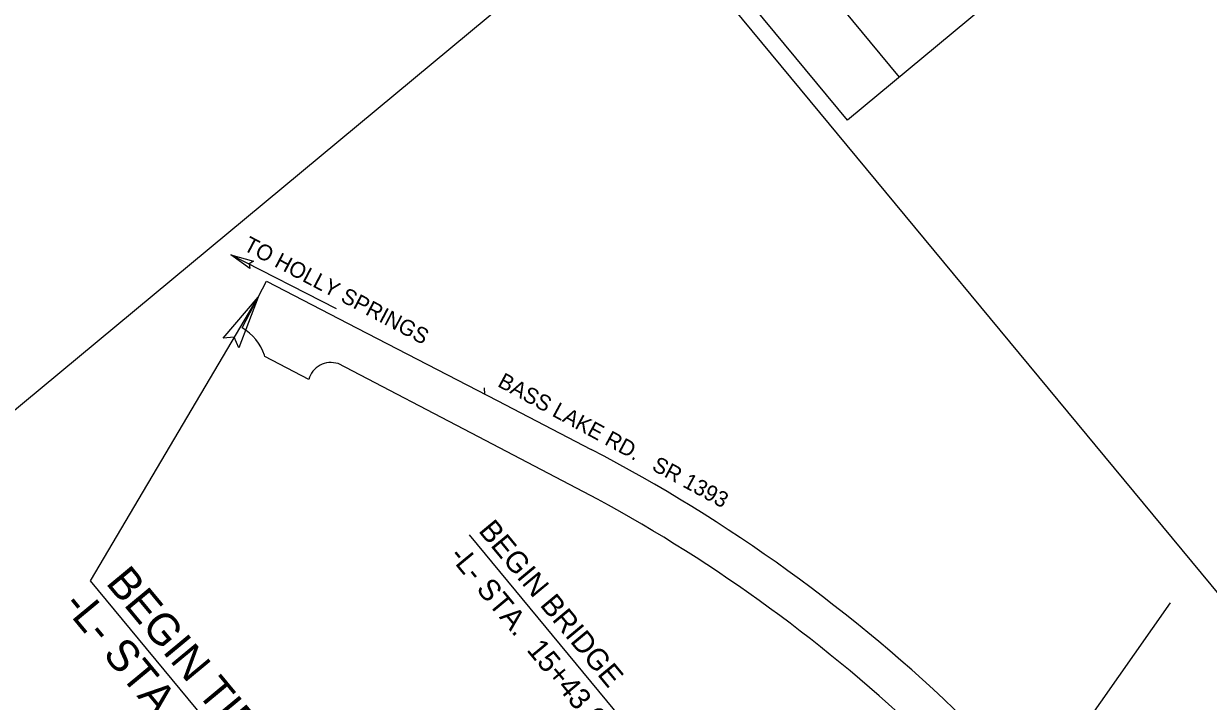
# Model space of a CAD drawing. Extents: x 2054826 to 2060231, y 685508 to 690809.
# Drawn here: x 2058198 to 2058951, y 688824 to 689255 of the extents above; entities that cross this region are included whole.
import ezdxf

# ---------------------------------------------------------------- set-up
doc = ezdxf.new("R2010")
doc.units = 0
for name, color, linetype in [('Default', 7, 'Continuous'), ('Old_Level_21', 7, 'Continuous'), ('Old_Level_9', 7, 'Continuous'), ('Prop Dimension Text', 7, 'Continuous'), ('Prop EOT', 7, 'Continuous'), ('Prop Horizontal Alignment Station Label', 7, 'Continuous'), ('Prop RDY Alternate Text Purple', 7, 'Continuous'), ('Prop Shade Medium', 7, 'Continuous'), ('Prop Terminator CELL', 7, 'Continuous')]:
    doc.layers.add(name, color=color, linetype=linetype)

msp = doc.modelspace()

# ---------------------------------------------------------------- linework, layer by layer
at = {"layer": 'Default'}
msp.add_line((2058396.86, 689073.63), (2058329.62, 689108), dxfattribs=at)
msp.add_lwpolyline([(2058776.37, 689968.05), (2059134.67, 689535.97), (2058721.62, 689193.45), (2058363.32, 689625.52)], close=True, dxfattribs=at)
at = {"layer": 'Old_Level_21'}
msp.add_line((2058396.35, 689652.92), (2058754.65, 689220.85), dxfattribs=at)
msp.add_lwpolyline([(2058588.27, 689338), (2059498.4, 688240.46), (2058988.43, 687817.56), (2058078.29, 688915.11)], close=True, dxfattribs=at)
at = {"layer": 'Prop Dimension Text'}
msp.add_line((2058481.13, 688930.04), (2058599, 688787.9), dxfattribs=at)
at = {"layer": 'Prop EOT'}
msp.add_line((2058490.77, 689023.53), (2058490.89, 689019.5), dxfattribs=at)
at = {"layer": 'Prop Horizontal Alignment Station Label'}
for p, q in [((2058240.57, 688900.83), (2058347.08, 689081.04)), ((2058478.6, 688613.8), (2058240.57, 688900.83))]:
    msp.add_line(p, q, dxfattribs=at)
at = {"layer": 'Prop RDY Alternate Text Purple'}
msp.add_line((2058817.56, 688730.88), (2058926.94, 688886.98), dxfattribs=at)
at = {"layer": 'Prop Shade Medium'}
for p, q in [((2058336.9, 689061.52), (2058352.41, 689091.33)), ((2058352.41, 689091.33), (2058410.1, 689061.38)), ((2058410.1, 689061.38), (2058498.98, 689015.49)), ((2058351.2, 689043.38), (2058351.07, 689044.18)), ((2058379.23, 689028.79), (2058351.2, 689043.38)), ((2058487.09, 688992.37), (2058397.82, 689038.83)), ((2058498.98, 689015.49), (2058558.82, 688984.35)), ((2058562.72, 688952.82), (2058487.09, 688992.37))]:
    msp.add_line(p, q, dxfattribs=at)
for centre, radius, start, end in [((2058321.43, 689034.42), 31.2, 18.22477, 60.28407), ((2058393.32, 689024.93), 14.61, 72.08021, 164.6698), ((2058091.62, 688086.65), 1012, 45.87384, 62.50587), ((2058091.62, 688086.65), 986, 46.39073, 61.45895)]:
    msp.add_arc(centre, radius, start, end, dxfattribs=at)
at = {"layer": 'Prop Terminator CELL'}
for points in [[(2058341.77, 689099.23), (2058329.62, 689108), (2058344.11, 689103.83), (2058341.26, 689102.31)], [(2058324.73, 689055.09), (2058347.06, 689081.06), (2058334.77, 689048.86), (2058331.84, 689055.64)]]:
    msp.add_lwpolyline(points, close=True, dxfattribs=at)

# ---------------------------------------------------------------- texts
at = {"layer": 'Default'}
msp.add_text('BASS LAKE RD.   SR 1393', height=10, rotation=331.5619, dxfattribs=at).set_placement((2058498.67, 689024.71))
at = {"layer": 'Old_Level_9'}
msp.add_text('TO HOLLY SPRINGS', height=10, rotation=332.23556, dxfattribs=at).set_placement((2058337.05, 689111.26))
at = {"layer": 'Prop Dimension Text'}
for s, p in [('BEGIN BRIDGE', (2058486.64, 688932.54)), ('-L- STA.  15+43.65', (2058467.93, 688916.39))]:
    msp.add_text(s, height=13.5, rotation=309.66721, dxfattribs=at).set_placement(p)
at = {"layer": 'Prop Horizontal Alignment Station Label'}
for s, p in [('BEGIN TIP PROJECT B-4659 ', (2058249.73, 688899.38)), ('-L- STA.  10+25.00  ', (2058222.17, 688884.99))]:
    msp.add_text(s, height=20, rotation=309.66721, dxfattribs=at).set_placement(p)

doc.saveas('drawing.dxf')
